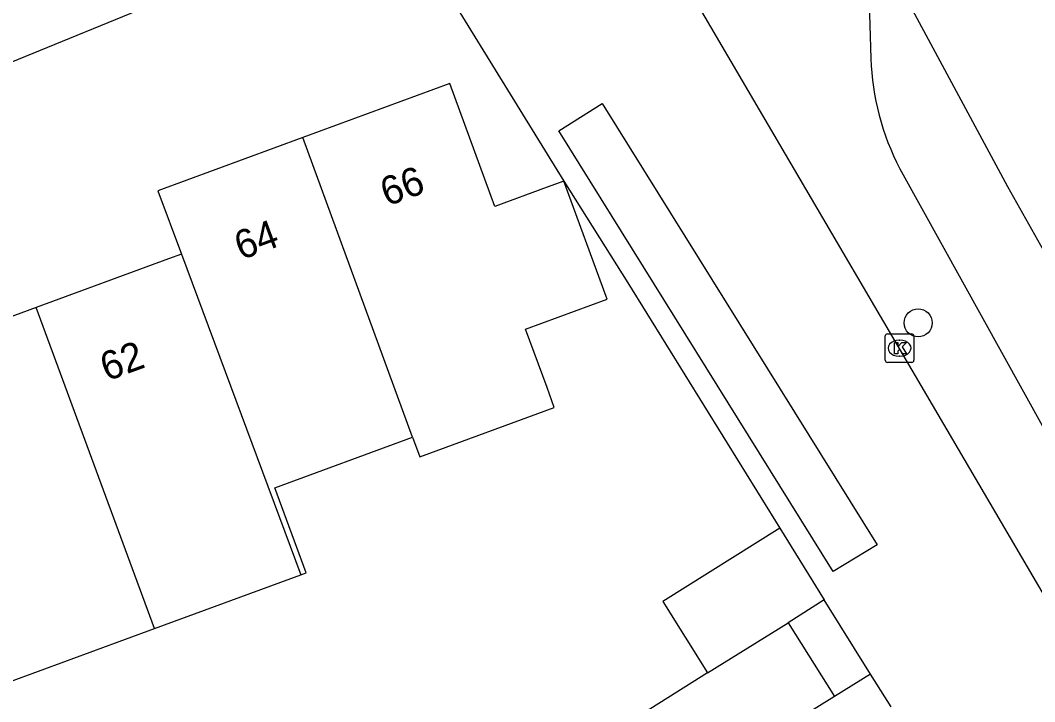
# Model space of a CAD drawing. Extents: x 157767 to 159171, y 387842 to 389425.
# Drawn here: x 158481.56 to 158517.05, y 388319.09 to 388342.92 of the extents above; entities that cross this region are included whole.
import ezdxf

# ---------------------------------------------------------------- set-up
doc = ezdxf.new("R2010")
doc.units = 0
for name, color, linetype in [('IMGEO_Boom', 7, 'Continuous'), ('IMGEO_Kolk', 7, 'Continuous'), ('IMGEO_Muur', 7, 'Continuous'), ('IMGEO_Pand', 7, 'Continuous'), ('IMGEO_Pand_nummerreeks', 7, 'Continuous'), ('IMGEO_Rijbaan_lokaal_gesloten', 7, 'Continuous'), ('IMGEO_Rijbaan_lokaal_open', 7, 'Continuous'), ('IMGEO_Voetpad_open', 7, 'Continuous')]:
    doc.layers.add(name, color=color, linetype=linetype)

msp = doc.modelspace()

# ---------------------------------------------------------------- linework, layer by layer
at = {"layer": 'IMGEO_Boom'}
msp.add_circle((158512.977, 388332.335), 0.489, dxfattribs=at)
at = {"layer": 'IMGEO_Kolk'}
for p, q in [((158511.901, 388331.951), (158512.753, 388331.951)), ((158511.826, 388331.025), (158511.826, 388331.877)), ((158512.314, 388331.731), (158512.339, 388331.731)), ((158512.827, 388331.877), (158512.827, 388331.025)), ((158512.753, 388330.951), (158511.901, 388330.951)), ((158512.337, 388331.171), (158512.312, 388331.171))]:
    msp.add_line(p, q, dxfattribs=at)
for points in [[(158511.901, 388331.951), (158512.753, 388331.951)], [(158511.826, 388331.025), (158511.826, 388331.877)], [(158512.147, 388331.651), (158512.27, 388331.651), (158512.27, 388331.5), (158512.4, 388331.651), (158512.564, 388331.651), (158512.418, 388331.5), (158512.571, 388331.251), (158512.419, 388331.251), (158512.334, 388331.415), (158512.27, 388331.348), (158512.27, 388331.251), (158512.147, 388331.251), (158512.147, 388331.651)], [(158512.827, 388331.877), (158512.827, 388331.025)], [(158512.753, 388330.951), (158511.901, 388330.951)]]:
    msp.add_lwpolyline(points, dxfattribs=at)
for centre, start, end in [((158511.903, 388331.875), 91.552, 178.448), ((158511.903, 388331.875), 91.552, 178.448), ((158512.751, 388331.875), 1.552, 88.448), ((158512.751, 388331.875), 1.552, 88.448), ((158511.903, 388331.027), 181.552, 268.448), ((158511.903, 388331.027), 181.552, 268.448), ((158512.751, 388331.027), 271.552, 358.448), ((158512.751, 388331.027), 271.552, 358.448)]:
    msp.add_arc(centre, 0.0765, start, end, dxfattribs=at)
for centre, major_axis, ratio, start_param, end_param in [((158512.313, 388331.451), (-0.387, 0.002), 0.722429, 4.712389, 7.853982), ((158512.338, 388331.451), (-0.39, 0.002), 0.717154, 1.570796, 4.712389)]:
    msp.add_ellipse(centre, major_axis=major_axis, ratio=ratio, start_param=start_param, end_param=end_param, dxfattribs=at)
at = {"layer": 'IMGEO_Muur'}
msp.add_lwpolyline([(158502.814, 388333.732), (158508.134, 388325.154)], dxfattribs=at)
at = {"layer": 'IMGEO_Pand'}
for points in [[(158500.583, 388337.29), (158500, 388337.076), (158498.168, 388336.403), (158496.589, 388340.702), (158491.449, 388338.814)], [(158491.449, 388338.814), (158486.376, 388336.95), (158487.2, 388334.737)], [(158495.283, 388328.34), (158491.449, 388338.814)], [(158495.283, 388328.34), (158495.536, 388327.648), (158500.244, 388329.371), (158500, 388330.073), (158499.238, 388332.119), (158502.098, 388333.166), (158502.065, 388333.257), (158500.583, 388337.29)], [(158487.2, 388334.737), (158486.751, 388334.572), (158482.115, 388332.869)], [(158487.2, 388334.737), (158491.374, 388323.524)], [(158482.115, 388332.869), (158477.051, 388331.009)], [(158486.263, 388321.646), (158482.115, 388332.869)], [(158491.374, 388323.524), (158491.56, 388323.592), (158490.466, 388326.571), (158495.283, 388328.34)], [(158508.134, 388325.154), (158504.046, 388322.595), (158505.612, 388320.092)], [(158508.134, 388325.154), (158509.684, 388322.644)], [(158486.263, 388321.646), (158491.374, 388323.524)], [(158509.684, 388322.644), (158508.434, 388321.842)], [(158481.184, 388319.781), (158486.263, 388321.646)], [(158505.612, 388320.092), (158508.434, 388321.842)], [(158508.434, 388321.842), (158510.045, 388319.266)], [(158505.612, 388320.092), (158502.511, 388318.15), (158504.118, 388315.572)], [(158510.045, 388319.266), (158504.118, 388315.572)]]:
    msp.add_lwpolyline(points, dxfattribs=at)
at = {"layer": 'IMGEO_Rijbaan_lokaal_gesloten'}
msp.add_lwpolyline([(158510.149, 388348.16), (158516.097, 388337.104), (158520.719, 388328.892), (158526.706, 388318.987), (158530.891, 388311.658), (158535.936, 388303.26)], dxfattribs=at)
msp.add_arc((158763.078, 388464.134), 272.859, 203.9844, 207.33977, dxfattribs=at)
at = {"layer": 'IMGEO_Rijbaan_lokaal_open'}
for points in [[(158532.05, 388297.782), (158526.372, 388307.483), (158502.602, 388348.033)], [(158427.533, 388319.501), (158491.882, 388345.812)], [(158496.17, 388344.444), (158500, 388338.235), (158500.583, 388337.29)], [(158510.005, 388323.64), (158500.409, 388339.055), (158501.926, 388340.01), (158511.546, 388324.569), (158510.005, 388323.64)], [(158500.583, 388337.29), (158502.814, 388333.732), (158508.134, 388325.154)], [(158511.308, 388320.053), (158509.684, 388322.644)], [(158512.028, 388318.905), (158511.308, 388320.053)]]:
    msp.add_lwpolyline(points, dxfattribs=at)
at = {"layer": 'IMGEO_Voetpad_open'}
for points in [[(158511.247, 388343.924), (158511.325, 388341.581)], [(158512.335, 388337.725), (158518.083, 388327.354), (158524.075, 388317.441), (158528.055, 388310.472)], [(158511.308, 388320.053), (158510.045, 388319.266)]]:
    msp.add_lwpolyline(points, dxfattribs=at)
msp.add_arc((158520.322, 388341.877), 9.002, 181.8869, 207.4686, dxfattribs=at)

# ---------------------------------------------------------------- texts
at = {"layer": 'IMGEO_Pand_nummerreeks'}
for s, p in [('66', (158494.391, 388336.4)), ('64', (158489.285, 388334.524)), ('62', (158484.589, 388330.283))]:
    msp.add_text(s, height=1, rotation=20.1681, dxfattribs=at).set_placement(p)

doc.saveas('drawing.dxf')
